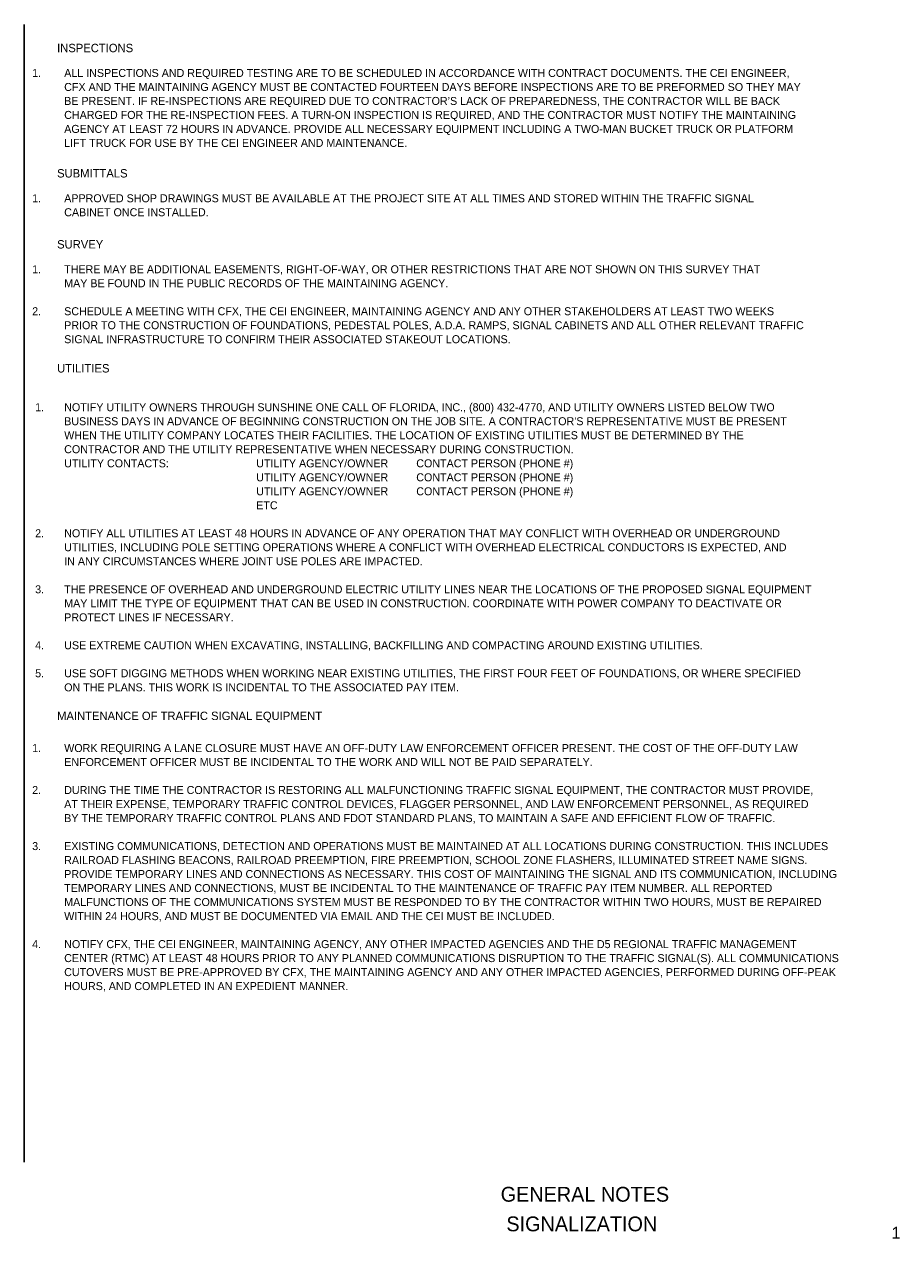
# Model space of a CAD drawing. Extents: x 2479946 to 2483081, y 3677527 to 3681234.
# Drawn here: x 2480771 to 2481509, y 3680210 to 3681234 of the extents above; entities that cross this region are included whole.
import ezdxf

# ---------------------------------------------------------------- set-up
doc = ezdxf.new("R2010")
doc.units = 0
for name, color, linetype in [('40', 7, 'Continuous'), ('ActivePointCell_dp', 7, 'Continuous'), ('RoadwayMisc', 7, 'Continuous'), ('TextMinor', 7, 'Continuous')]:
    doc.layers.add(name, color=color, linetype=linetype)

msp = doc.modelspace()

# ---------------------------------------------------------------- linework, layer by layer
at = {"layer": 'ActivePointCell_dp'}
msp.add_line((2480770.9, 3680274.2), (2480770.9, 3681234.2), dxfattribs=at)

# ---------------------------------------------------------------- texts
at = {"layer": '40'}
for s, height, p in [('INSPECTIONS', 7.08, (2480798.6, 3681210.7)), ('1.', 6.75, (2480777.6, 3681189.8)), ('ALL INSPECTIONS AND REQUIRED TESTING ARE TO BE SCHEDULED IN ACCORDANCE WITH CONTRACT DOCUMENTS. THE CEI ENGINEER, ', 6.75, (2480804.6, 3681189.8)), ('CFX AND THE MAINTAINING AGENCY MUST BE CONTACTED FOURTEEN DAYS BEFORE INSPECTIONS ARE TO BE PREFORMED SO THEY MAY ', 6.75, (2480804.6, 3681178)), ('BE PRESENT. IF RE-INSPECTIONS ARE REQUIRED DUE TO CONTRACTOR’S LACK OF PREPAREDNESS, THE CONTRACTOR WILL BE BACK ', 6.75, (2480804.6, 3681166.2)), ('CHARGED FOR THE RE-INSPECTION FEES. A TURN-ON INSPECTION IS REQUIRED, AND THE CONTRACTOR MUST NOTIFY THE MAINTAINING ', 6.75, (2480804.6, 3681154.4)), ('AGENCY AT LEAST 72 HOURS IN ADVANCE. PROVIDE ALL NECESSARY EQUIPMENT INCLUDING A TWO-MAN BUCKET TRUCK OR PLATFORM ', 6.75, (2480804.6, 3681142.6)), ('LIFT TRUCK FOR USE BY THE CEI ENGINEER AND MAINTENANCE. ', 6.75, (2480804.6, 3681130.8)), ('SUBMITTALS', 7.08, (2480798.6, 3681105)), ('1.', 6.75, (2480777.6, 3681084.1)), ('APPROVED SHOP DRAWINGS MUST BE AVAILABLE AT THE PROJECT SITE AT ALL TIMES AND STORED WITHIN THE TRAFFIC SIGNAL ', 6.75, (2480804.6, 3681084.1)), ('CABINET ONCE INSTALLED.', 6.75, (2480804.6, 3681072.3)), ('SURVEY', 7.08, (2480798.6, 3681045.1)), ('1.', 6.75, (2480777.6, 3681024.2)), ('THERE MAY BE ADDITIONAL EASEMENTS, RIGHT-OF-WAY, OR OTHER RESTRICTIONS THAT ARE NOT SHOWN ON THIS SURVEY THAT ', 6.75, (2480804.6, 3681024.2)), ('MAY BE FOUND IN THE PUBLIC RECORDS OF THE MAINTAINING AGENCY.', 6.75, (2480804.6, 3681012.4)), ('2.', 6.75, (2480777.6, 3680988.8)), ('SCHEDULE A MEETING WITH CFX, THE CEI ENGINEER, MAINTAINING AGENCY AND ANY OTHER STAKEHOLDERS AT LEAST TWO WEEKS ', 6.75, (2480804.6, 3680988.8)), ('PRIOR TO THE CONSTRUCTION OF FOUNDATIONS, PEDESTAL POLES, A.D.A. RAMPS, SIGNAL CABINETS AND ALL OTHER RELEVANT TRAFFIC ', 6.75, (2480804.6, 3680977)), ('SIGNAL INFRASTRUCTURE TO CONFIRM THEIR ASSOCIATED STAKEOUT LOCATIONS.', 6.75, (2480804.6, 3680965.2)), ('UTILITIES', 7.08, (2480798.6, 3680940.5)), ('1.', 6.75, (2480780.1, 3680907.8)), ('NOTIFY UTILITY OWNERS THROUGH SUNSHINE ONE CALL OF FLORIDA, INC., (800) 432-4770, AND UTILITY OWNERS LISTED BELOW TWO ', 6.75, (2480804.6, 3680907.8)), ("BUSINESS DAYS IN ADVANCE OF BEGINNING CONSTRUCTION ON THE JOB SITE. A CONTRACTOR'S REPRESENTATIVE MUST BE PRESENT ", 6.75, (2480804.6, 3680896)), ('WHEN THE UTILITY COMPANY LOCATES THEIR FACILITIES. THE LOCATION OF EXISTING UTILITIES MUST BE DETERMINED BY THE ', 6.75, (2480804.6, 3680884.2)), ('CONTRACTOR AND THE UTILITY REPRESENTATIVE WHEN NECESSARY DURING CONSTRUCTION.', 6.75, (2480804.6, 3680872.4)), ('UTILITY CONTACTS: ', 6.75, (2480804.6, 3680860.5)), ('UTILITY AGENCY/OWNER', 6.75, (2480966.6, 3680860.5)), ('CONTACT PERSON (PHONE #)', 6.75, (2481101.6, 3680860.5)), ('UTILITY AGENCY/OWNER', 6.75, (2480966.6, 3680848.7)), ('CONTACT PERSON (PHONE #)', 6.75, (2481101.6, 3680848.7)), ('UTILITY AGENCY/OWNER', 6.75, (2480966.6, 3680836.9)), ('CONTACT PERSON (PHONE #)', 6.75, (2481101.6, 3680836.9)), ('ETC', 6.75, (2480966.6, 3680825.1)), ('2.', 6.75, (2480780.1, 3680801.5)), ('NOTIFY ALL UTILITIES AT LEAST 48 HOURS IN ADVANCE OF ANY OPERATION THAT MAY CONFLICT WITH OVERHEAD OR UNDERGROUND ', 6.75, (2480804.6, 3680801.5)), ('UTILITIES, INCLUDING POLE SETTING OPERATIONS WHERE A CONFLICT WITH OVERHEAD ELECTRICAL CONDUCTORS IS EXPECTED, AND ', 6.75, (2480804.6, 3680789.7)), ('IN ANY CIRCUMSTANCES WHERE JOINT USE POLES ARE IMPACTED.', 6.75, (2480804.6, 3680777.9)), ('3.', 6.75, (2480780.1, 3680754.2)), ('THE PRESENCE OF OVERHEAD AND UNDERGROUND ELECTRIC UTILITY LINES NEAR THE LOCATIONS OF THE PROPOSED SIGNAL EQUIPMENT ', 6.75, (2480804.6, 3680754.2)), ('MAY LIMIT THE TYPE OF EQUIPMENT THAT CAN BE USED IN CONSTRUCTION. COORDINATE WITH POWER COMPANY TO DEACTIVATE OR ', 6.75, (2480804.6, 3680742.4)), ('PROTECT LINES IF NECESSARY.', 6.75, (2480804.6, 3680730.6)), ('4.', 6.75, (2480780.1, 3680707)), ('USE EXTREME CAUTION WHEN EXCAVATING, INSTALLING, BACKFILLING AND COMPACTING AROUND EXISTING UTILITIES.', 6.75, (2480804.6, 3680707)), ('5.', 6.75, (2480780.1, 3680683.4)), ('USE SOFT DIGGING METHODS WHEN WORKING NEAR EXISTING UTILITIES, THE FIRST FOUR FEET OF FOUNDATIONS, OR WHERE SPECIFIED ', 6.75, (2480804.6, 3680683.4)), ('ON THE PLANS. THIS WORK IS INCIDENTAL TO THE ASSOCIATED PAY ITEM. ', 6.75, (2480804.6, 3680671.5)), ('MAINTENANCE OF TRAFFIC SIGNAL EQUIPMENT', 7.08, (2480798.6, 3680647.3)), ('1.', 6.75, (2480777.6, 3680620.3)), ('WORK REQUIRING A LANE CLOSURE MUST HAVE AN OFF-DUTY LAW ENFORCEMENT OFFICER PRESENT. THE COST OF THE OFF-DUTY LAW ', 6.75, (2480804.6, 3680620.3)), ('ENFORCEMENT OFFICER MUST BE INCIDENTAL TO THE WORK AND WILL NOT BE PAID SEPARATELY.', 6.75, (2480804.6, 3680608.5)), ('2.', 6.75, (2480777.6, 3680584.9)), ('DURING THE TIME THE CONTRACTOR IS RESTORING ALL MALFUNCTIONING TRAFFIC SIGNAL EQUIPMENT, THE CONTRACTOR MUST PROVIDE, ', 6.75, (2480804.6, 3680584.9)), ('AT THEIR EXPENSE, TEMPORARY TRAFFIC CONTROL DEVICES, FLAGGER PERSONNEL, AND LAW ENFORCEMENT PERSONNEL, AS REQUIRED ', 6.75, (2480804.6, 3680573)), ('BY THE TEMPORARY TRAFFIC CONTROL PLANS AND FDOT STANDARD PLANS, TO MAINTAIN A SAFE AND EFFICIENT FLOW OF TRAFFIC. ', 6.75, (2480804.6, 3680561.2)), ('3.', 6.75, (2480777.6, 3680537.6)), ('EXISTING COMMUNICATIONS, DETECTION AND OPERATIONS MUST BE MAINTAINED AT ALL LOCATIONS DURING CONSTRUCTION. THIS INCLUDES ', 6.75, (2480804.6, 3680537.6)), ('RAILROAD FLASHING BEACONS, RAILROAD PREEMPTION, FIRE PREEMPTION, SCHOOL ZONE FLASHERS, ILLUMINATED STREET NAME SIGNS. ', 6.75, (2480804.6, 3680525.8)), ('PROVIDE TEMPORARY LINES AND CONNECTIONS AS NECESSARY. THIS COST OF MAINTAINING THE SIGNAL AND ITS COMMUNICATION, INCLUDING ', 6.75, (2480804.6, 3680514)), ('TEMPORARY LINES AND CONNECTIONS, MUST BE INCIDENTAL TO THE MAINTENANCE OF TRAFFIC PAY ITEM NUMBER. ALL REPORTED ', 6.75, (2480804.6, 3680502.2)), ('MALFUNCTIONS OF THE COMMUNICATIONS SYSTEM MUST BE RESPONDED TO BY THE CONTRACTOR WITHIN TWO HOURS, MUST BE REPAIRED ', 6.75, (2480804.6, 3680490.4)), ('WITHIN 24 HOURS, AND MUST BE DOCUMENTED VIA EMAIL AND THE CEI MUST BE INCLUDED. ', 6.75, (2480804.6, 3680478.5)), ('4.', 6.75, (2480777.6, 3680454.9)), ('NOTIFY CFX, THE CEI ENGINEER, MAINTAINING AGENCY, ANY OTHER IMPACTED AGENCIES AND THE D5 REGIONAL TRAFFIC MANAGEMENT ', 6.75, (2480804.6, 3680454.9)), ('CENTER (RTMC) AT LEAST 48 HOURS PRIOR TO ANY PLANNED COMMUNICATIONS DISRUPTION TO THE TRAFFIC SIGNAL(S). ALL COMMUNICATIONS ', 6.75, (2480804.6, 3680443.1)), ('CUTOVERS MUST BE PRE-APPROVED BY CFX, THE MAINTAINING AGENCY AND ANY OTHER IMPACTED AGENCIES, PERFORMED DURING OFF-PEAK ', 6.75, (2480804.6, 3680431.3)), ('HOURS, AND COMPLETED IN AN EXPEDIENT MANNER.', 6.75, (2480804.6, 3680419.5))]:
    msp.add_text(s, height=height, dxfattribs=at).set_placement(p)
at = {"layer": 'RoadwayMisc'}
msp.add_text('1', height=10, rotation=360, dxfattribs=at).set_placement((2481502.6, 3680209.8))
at = {"layer": 'TextMinor'}
for s, p in [('     GENERAL NOTES      ', (2481149.6, 3680241)), ('     SIGNALIZATION      ', (2481154.4, 3680216))]:
    msp.add_text(s, height=12.5, rotation=360, dxfattribs=at).set_placement(p)

doc.saveas('drawing.dxf')
